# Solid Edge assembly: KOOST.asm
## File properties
Author: ke06
Template: normal.asm
Last saved by: Andris
Revision: 15
Application: Solid Edge
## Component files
stekas_mir.par
stekas.par
pohi.par
KABIIN.par
MAST.par
PURI.psm
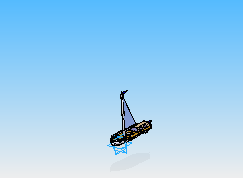
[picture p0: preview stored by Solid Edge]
